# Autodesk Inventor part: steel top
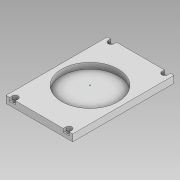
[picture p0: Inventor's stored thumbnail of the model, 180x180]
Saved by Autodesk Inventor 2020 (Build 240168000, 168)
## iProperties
Created: 2019-12
Part Number: steel top
Material: Generic
Document SubType Name: Modeling
Designer: MPI
Density: 1 g/cm^3
Appearance: Default
Author: MPI
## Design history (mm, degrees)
sketch "Sketch1"
  geometry: L1 (79.375, 120.65)-(-79.375, 120.65); L2 (-79.375, 120.65)-(-79.375, -120.65); L3 (-79.375, -120.65)-(79.375, -120.65); L4 (79.375, -120.65)-(79.375, 120.65); L5 (79.375, 120.65)-(-79.375, -120.65); L6 (79.375, -120.65)-(-79.375, 120.65); 2 further points
  constraints: 12 end point, 2 parallel, 1 coincident, 1 horizontal, 1 midpoint, 1 perpendicular
  dimensions: "d0" = 158.75 distance of L2.end L3.end; "d1" = 241.3 distance of L3.end L1.start
extrude "Extrusion1" new body sketch "Sketch1" distance "d2" = 16.51; taper "d3" = 0 deg
sketch "Sketch2"
  geometry: C1 r 67.31 at (0, 0); 1 further point
  constraints: 1 centre point, 1 coincident
  dimensions: "d4" = 134.62 diameter of C1
extrude "Extrusion2" cut sketch "Sketch2" distance "d5" = 13.97; taper "d6" = 0 deg
sketch "Sketch3"
  geometry: C1 r 76.2 at (0, 0); 1 further point
  constraints: 1 centre point, 1 coincident
  dimensions: "d7" = 152.4 diameter of C1
extrude "Extrusion3" join sketch "Sketch3" distance "d8" = 2.54; taper "d9" = 0 deg
sketch "Sketch4"
  geometry: 1 further point
sketch "Sketch5"
  geometry: L1 (-170.419, -114.3)-(194.918, -114.3); L2 (-157.706, 114.3)-(189.565, 114.3); L3 (64.135, 174.59)-(64.135, -208.144); L4 (-64.135, 174.59)-(-64.135, -208.144); L5 (-79.375, -120.65)-(79.375, -120.65) reference; L6 (79.375, 120.65)-(-79.375, 120.65) reference; L7 (79.375, -120.65)-(79.375, 120.65) reference; L8 (-79.375, 120.65)-(-79.375, -120.65) reference; 5 further points
  constraints: 8 end point, 8 point on line, 2 horizontal, 2 vertical
  dimensions: "d17" = 6.35 distance between parallel lines of L5 L1; "d18" = 6.35 distance between parallel lines of L6 L2; "d19" = 15.24 distance between parallel lines of L7 L3; "d20" = 15.24 distance between parallel lines of L4 L8
hole "Hole1" sketch "Sketch5" at (-64.135, -114.3), (64.135, -114.3), (64.135, 114.3), (-64.135, 114.3) diameter "d10" = 8.7376; stored, may be unused: countersink angle "d14" = 82 deg, drill point angle "d16" = 118 deg; dims "d11" = 19.05, "d12" = 13.97, "d13" = 8.382, "d15" = 22.86
sketch "Sketch6"
  geometry: L1 (-71.12, 124.46)-(-57.15, 124.46); L2 (-57.15, 124.46)-(-57.15, 114.3); L3 (-57.15, 114.3)-(-71.12, 114.3); L4 (-71.12, 114.3)-(-71.12, 124.46); L5 (57.15, 124.46)-(71.12, 124.46); L6 (71.12, 124.46)-(71.12, 114.3); L7 (71.12, 114.3)-(57.15, 114.3); L8 (57.15, 114.3)-(57.15, 124.46); L9 (57.15, -114.3)-(71.12, -114.3); L10 (71.12, -114.3)-(71.12, -124.46); L11 (71.12, -124.46)-(57.15, -124.46); L12 (57.15, -124.46)-(57.15, -114.3); L13 (-71.12, -114.3)-(-57.15, -114.3); L14 (-57.15, -114.3)-(-57.15, -124.46); L15 (-57.15, -124.46)-(-71.12, -124.46); L16 (-71.12, -124.46)-(-71.12, -114.3); A1 r 6.985 centre (-64.135, 114.3) between (-67.045, 120.65) and (-61.225, 120.65) reference; A2 r 6.985 centre (64.135, 114.3) between (61.225, 120.65) and (67.045, 120.65) reference; A3 r 6.985 centre (64.135, -114.3) between (67.045, -120.65) and (61.225, -120.65) reference; A4 r 6.985 centre (-64.135, -114.3) between (-61.225, -120.65) and (-67.045, -120.65) reference; 2 further points
  constraints: 32 end point, 8 parallel, 8 tangent, 4 horizontal, 4 midpoint, 4 perpendicular, 3 equal length, 1 coincident
  dimensions: "d21" = 10.16 distance of L9.end L10.end
extrude "Extrusion4" cut sketch "Sketch6" stored distance "d22" = 25.4; taper "d23" = 0 deg
body "Solid1"
